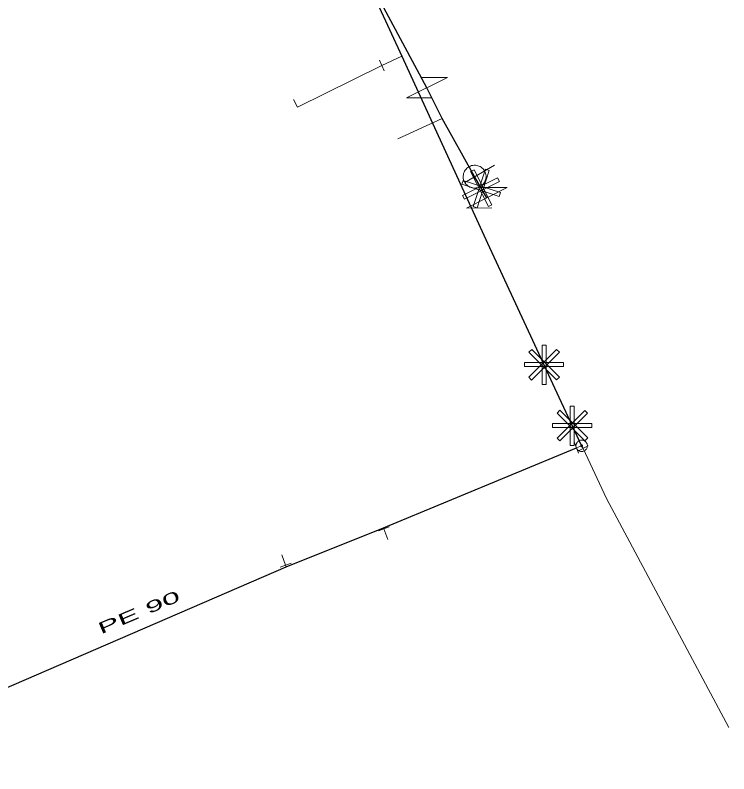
# Model space of a CAD drawing. Extents: x -809028 to -807737, y -990545 to -989489.
# Drawn here: x -808619.4 to -808556.9, y -990104.7 to -990038.3 of the extents above; entities that cross this region are included whole.
import ezdxf

# ---------------------------------------------------------------- set-up
doc = ezdxf.new("R2010")
doc.units = 0
doc.header["$LTSCALE"] = 0.32
for name, color, linetype, lineweight in [('1', 7, 'Continuous', 13), ('10', 7, 'Continuous', 13), ('11', 7, 'Continuous', 13), ('12', 7, 'Continuous', 13), ('13', 7, 'Continuous', 13), ('14', 7, 'Continuous', 25), ('17', 7, 'Continuous', 25), ('22', 7, 'Continuous', 13), ('31', 7, 'Continuous', 13), ('34', 7, 'Continuous', 13), ('47', 7, 'Continuous', 13)]:
    doc.layers.add(name, color=color, linetype=linetype, lineweight=lineweight)

msp = doc.modelspace()

# ---------------------------------------------------------------- linework, layer by layer
at = {"layer": '10'}
for points in [[(-808577.671, -990054.895), (-808577.984, -990055.053), (-808579.535, -990051.989), (-808579.223, -990051.83)], [(-808578.235, -990051.776), (-808577.902, -990051.885), (-808578.972, -990055.149), (-808579.305, -990055.041)], [(-808577.176, -990052.533), (-808577.018, -990052.845), (-808580.083, -990054.396), (-808580.241, -990054.084)], [(-808576.929, -990053.827), (-808577.038, -990054.16), (-808580.302, -990053.09), (-808580.193, -990052.757)]]:
    msp.add_lwpolyline(points, close=True, dxfattribs=at)
at = {"layer": '11'}
msp.add_line((-808585.911, -990049.136), (-808582.017, -990047.352), dxfattribs=at)
at = {"layer": '12'}
for points in [[(-808572.018, -990067.557), (-808571.77, -990067.805), (-808574.199, -990070.234), (-808574.446, -990069.986)], [(-808574.437, -990067.796), (-808574.19, -990067.548), (-808571.761, -990069.977), (-808572.008, -990070.225)], [(-808573.284, -990067.193), (-808572.934, -990067.193), (-808572.934, -990070.628), (-808573.284, -990070.628)], [(-808571.4, -990068.702), (-808571.4, -990069.052), (-808574.835, -990069.052), (-808574.835, -990068.702)], [(-808569.545, -990072.885), (-808569.297, -990073.133), (-808571.726, -990075.562), (-808571.973, -990075.314)], [(-808571.964, -990073.124), (-808571.717, -990072.876), (-808569.288, -990075.305), (-808569.535, -990075.553)], [(-808570.811, -990072.521), (-808570.461, -990072.521), (-808570.461, -990075.956), (-808570.811, -990075.956)], [(-808568.927, -990074.03), (-808568.927, -990074.38), (-808572.362, -990074.38), (-808572.362, -990074.03)]]:
    msp.add_lwpolyline(points, close=True, dxfattribs=at)
at = {"layer": '13'}
for p, q in [((-808585.563, -990041.877), (-808587.298, -990042.704)), ((-808587.129, -990083.26), (-808586.789, -990084.199)), ((-808595.719, -990086.43), (-808596.059, -990085.53))]:
    msp.add_line(p, q, dxfattribs=at)
for points in [[(-808587.298, -990042.704), (-808594.677, -990046.338), (-808595.022, -990045.688)], [(-808569.699, -990076.229), (-808567.649, -990080.609), (-808556.943, -990100.651)]]:
    msp.add_lwpolyline(points, dxfattribs=at)
at = {"layer": '14'}
msp.add_line((-808578.12, -990054.282), (-808579.186, -990052.432), dxfattribs=at)
at = {"layer": '14', "lineweight": 13}
for p, q in [((-808569.819, -990075.989), (-808570.269, -990076.169)), ((-808569.819, -990075.989), (-808569.699, -990076.229)), ((-808587.16, -990083.18), (-808587.129, -990083.26)), ((-808595.67, -990086.57), (-808595.719, -990086.43))]:
    msp.add_line(p, q, dxfattribs=at)
at = {"layer": '14'}
for points in [[(-808583.364, -990044.645), (-808587.566, -990036.813), (-808597.186, -990015.591)], [(-808579.186, -990052.432), (-808582.017, -990047.352), (-808583.364, -990044.645)]]:
    msp.add_lwpolyline(points, dxfattribs=at)
at = {"layer": '17'}
for points in [[(-808605.01, -990001.965), (-808595.743, -990019.989), (-808592.335, -990027.23), (-808591.921, -990028.11), (-808591.508, -990029.003), (-808585.563, -990041.877), (-808578.065, -990058.263), (-808574.107, -990066.738), (-808572.19, -990070.92), (-808570.028, -990075.541), (-808569.819, -990075.989)], [(-808701.855, -990060.506), (-808701.829, -990060.681), (-808697.27, -990069.28), (-808693.69, -990076.03), (-808687.44, -990085.39), (-808684.289, -990089.78), (-808678.76, -990094.309), (-808670.239, -990099.57), (-808661.14, -990102.75), (-808654.14, -990104.289), (-808648.629, -990104.699), (-808647.25, -990104.6), (-808641.89, -990104.3), (-808635.76, -990103.28), (-808622.739, -990098.27), (-808595.67, -990086.57), (-808587.16, -990083.18), (-808570.269, -990076.169)]]:
    msp.add_lwpolyline(points, dxfattribs=at)
at = {"layer": '22'}
msp.add_line((-808577.452, -990051.433), (-808580.052, -990052.93), dxfattribs=at)
msp.add_lwpolyline([(-808579.684, -990051.565), (-808579.775, -990051.624), (-808579.86, -990051.694), (-808579.937, -990051.773), (-808580.005, -990051.858), (-808580.063, -990051.951), (-808580.11, -990052.05), (-808580.146, -990052.154), (-808580.17, -990052.26), (-808580.183, -990052.369), (-808580.184, -990052.478), (-808580.173, -990052.587), (-808580.149, -990052.694), (-808580.115, -990052.798), (-808580.069, -990052.898), (-808580.013, -990052.992), (-808579.947, -990053.079), (-808579.872, -990053.159), (-808579.788, -990053.23), (-808579.697, -990053.29), (-808579.601, -990053.341), (-808579.498, -990053.381), (-808579.393, -990053.409), (-808579.284, -990053.426), (-808579.175, -990053.431), (-808579.066, -990053.424), (-808578.958, -990053.405), (-808578.852, -990053.374), (-808578.752, -990053.332), (-808578.655, -990053.279), (-808578.566, -990053.216), (-808578.484, -990053.144), (-808578.411, -990053.063), (-808578.346, -990052.975), (-808578.291, -990052.88), (-808578.248, -990052.779), (-808578.215, -990052.675), (-808578.194, -990052.567), (-808578.185, -990052.458), (-808578.188, -990052.349), (-808578.204, -990052.24), (-808578.23, -990052.134), (-808578.268, -990052.031), (-808578.318, -990051.933), (-808578.378, -990051.842), (-808578.447, -990051.757), (-808578.525, -990051.681), (-808578.611, -990051.613), (-808578.704, -990051.554), (-808578.803, -990051.507), (-808578.906, -990051.471), (-808579.013, -990051.446), (-808579.121, -990051.433), (-808579.231, -990051.432), (-808579.339, -990051.444), (-808579.447, -990051.466), (-808579.551, -990051.501), (-808579.651, -990051.547)], close=True, dxfattribs=at)
at = {"layer": '31'}
for points in [[(-808582.918, -990045.54), (-808585.154, -990045.535), (-808581.572, -990043.754), (-808583.808, -990043.749)], [(-808578.57, -990053.389), (-808576.334, -990053.382), (-808579.906, -990055.181), (-808577.67, -990055.175)]]:
    msp.add_lwpolyline(points, dxfattribs=at)
at = {"layer": '34'}
for p, q in [((-808587.509, -990042.25), (-808587.087, -990043.157)), ((-808570.455, -990075.704), (-808570.083, -990076.633)), ((-808569.256, -990075.997), (-808570.142, -990076.46)), ((-808586.661, -990083.083), (-808587.597, -990083.435)), ((-808595.248, -990086.261), (-808596.19, -990086.597))]:
    msp.add_line(p, q, dxfattribs=at)
at = {"layer": '47'}
for points in [[(-808569.607, -990076.442), (-808569.561, -990076.417), (-808569.518, -990076.388), (-808569.478, -990076.354), (-808569.441, -990076.317), (-808569.409, -990076.275), (-808569.381, -990076.23), (-808569.359, -990076.184), (-808569.341, -990076.134), (-808569.328, -990076.084), (-808569.32, -990076.032), (-808569.319, -990075.979), (-808569.323, -990075.927), (-808569.331, -990075.876), (-808569.346, -990075.826), (-808569.365, -990075.777), (-808569.39, -990075.731), (-808569.419, -990075.688), (-808569.454, -990075.647), (-808569.49, -990075.611), (-808569.532, -990075.579), (-808569.577, -990075.551), (-808569.624, -990075.528), (-808569.673, -990075.51), (-808569.723, -990075.497), (-808569.775, -990075.49), (-808569.828, -990075.489), (-808569.88, -990075.492), (-808569.931, -990075.501), (-808569.981, -990075.516), (-808570.03, -990075.535), (-808570.076, -990075.56), (-808570.119, -990075.589), (-808570.16, -990075.623), (-808570.196, -990075.66), (-808570.228, -990075.702), (-808570.256, -990075.746), (-808570.279, -990075.793), (-808570.297, -990075.842), (-808570.31, -990075.893), (-808570.317, -990075.945), (-808570.318, -990075.998), (-808570.315, -990076.049), (-808570.306, -990076.101), (-808570.291, -990076.151), (-808570.272, -990076.2), (-808570.247, -990076.246), (-808570.218, -990076.289), (-808570.185, -990076.329), (-808570.147, -990076.366), (-808570.105, -990076.398), (-808570.061, -990076.426), (-808570.014, -990076.448), (-808569.965, -990076.466), (-808569.914, -990076.479), (-808569.862, -990076.487), (-808569.809, -990076.488), (-808569.758, -990076.484), (-808569.706, -990076.476), (-808569.656, -990076.461)], [(-808569.784, -990076.063), (-808569.776, -990076.059), (-808569.769, -990076.054), (-808569.763, -990076.049), (-808569.757, -990076.043), (-808569.751, -990076.036), (-808569.747, -990076.028), (-808569.743, -990076.021), (-808569.74, -990076.013), (-808569.738, -990076.004), (-808569.737, -990075.996), (-808569.737, -990075.987), (-808569.737, -990075.978), (-808569.739, -990075.97), (-808569.74, -990075.962), (-808569.744, -990075.954), (-808569.748, -990075.946), (-808569.753, -990075.939), (-808569.758, -990075.933), (-808569.764, -990075.927), (-808569.771, -990075.921), (-808569.779, -990075.917), (-808569.786, -990075.913), (-808569.794, -990075.91), (-808569.803, -990075.907), (-808569.811, -990075.907), (-808569.82, -990075.907), (-808569.829, -990075.907), (-808569.837, -990075.909), (-808569.845, -990075.91), (-808569.853, -990075.914), (-808569.861, -990075.918), (-808569.868, -990075.923), (-808569.874, -990075.928), (-808569.88, -990075.934), (-808569.886, -990075.941), (-808569.89, -990075.948), (-808569.894, -990075.956), (-808569.897, -990075.964), (-808569.9, -990075.973), (-808569.9, -990075.981), (-808569.9, -990075.99), (-808569.9, -990075.999), (-808569.898, -990076.007), (-808569.897, -990076.015), (-808569.893, -990076.023), (-808569.889, -990076.031), (-808569.884, -990076.038), (-808569.879, -990076.044), (-808569.873, -990076.05), (-808569.866, -990076.056), (-808569.859, -990076.06), (-808569.851, -990076.064), (-808569.843, -990076.067), (-808569.834, -990076.069), (-808569.826, -990076.07), (-808569.817, -990076.07), (-808569.808, -990076.07), (-808569.8, -990076.068), (-808569.792, -990076.067)]]:
    msp.add_lwpolyline(points, close=True, dxfattribs=at)

# ---------------------------------------------------------------- texts
at = {"layer": '1', "width": 2.1}
msp.add_text('PE 90 ', height=1, rotation=23, dxfattribs=at).set_placement((-808611.89, -990092.506))

doc.saveas('drawing.dxf')
